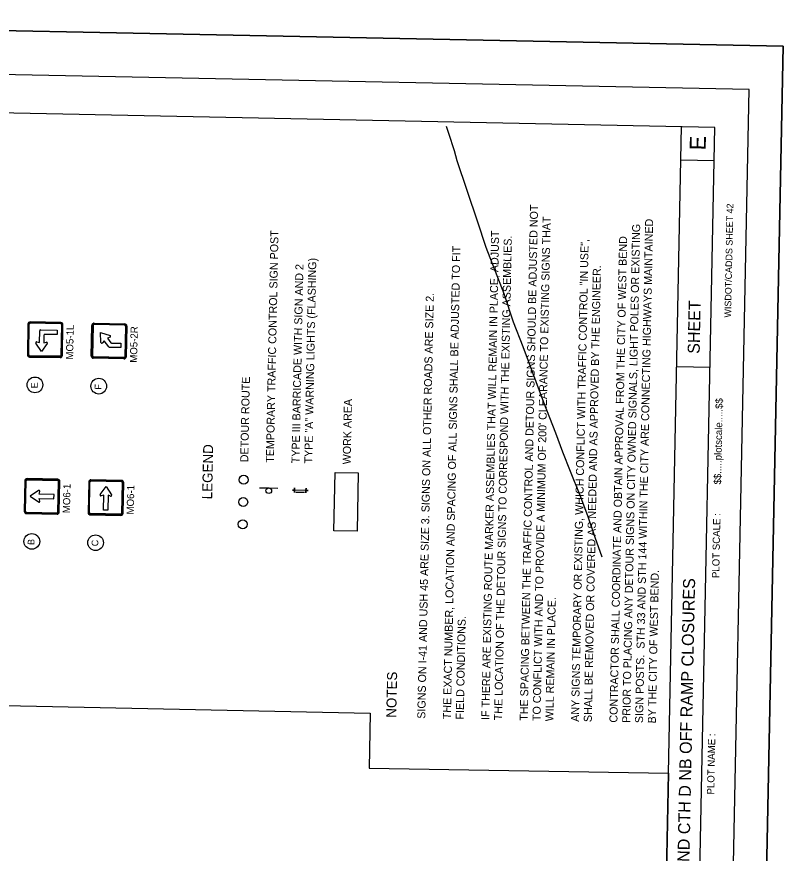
# Model space of a CAD drawing. Extents: x 327762 to 372792, y 127949 to 259367.
# Drawn here: x 358431 to 372792, y 195702 to 211374 of the extents above; entities that cross this region are included whole.
import ezdxf

# ---------------------------------------------------------------- set-up
doc = ezdxf.new("R2010")
doc.units = 0
for name, color, linetype in [('CA-TEXT', 7, 'Continuous'), ('CE-TOPO-CONC-SLAB', 7, 'Continuous'), ('Level 1', 7, 'Continuous'), ('P_MISC_NoPlot', 7, 'Continuous'), ('P_RDWY_Text', 7, 'Continuous'), ('P_SGN_Cell', 7, 'Continuous'), ('P_TC', 7, 'Continuous'), ('PLT_Sheet_Border', 7, 'Continuous'), ('PLT_Sheet_Info', 7, 'Continuous'), ('SIGNS-POLES', 7, 'Continuous')]:
    doc.layers.add(name, color=color, linetype=linetype)

msp = doc.modelspace()

# ---------------------------------------------------------------- linework, layer by layer
at = {"layer": 'CA-TEXT'}
for centre in [(358773, 204477), (359968, 204453), (358714, 201544), (359909, 201520)]:
    msp.add_circle(centre, 147, dxfattribs=at)
at = {"layer": 'CE-TOPO-CONC-SLAB'}
for centre in [(362683, 202699), (362674, 202282), (362666, 201865)]:
    msp.add_circle(centre, 83.7, dxfattribs=at)
at = {"layer": 'Level 1'}
for points in [[(367735, 205650), (367564, 206185), (367228, 207053), (367066, 207544), (366680, 208672), (366630, 208860), (366529, 209184), (366482, 209319)], [(369268, 201620), (369131, 202025), (368989, 202402), (368805, 202851), (368663, 203217), (368530, 203572), (368306, 204147), (368164, 204534), (368103, 204701), (367920, 205192), (367735, 205650)], [(369401, 201251), (369268, 201620)]]:
    msp.add_lwpolyline(points, dxfattribs=at)
at = {"layer": 'P_MISC_NoPlot'}
msp.add_lwpolyline([(345724, 170440), (346294, 198721), (365051, 198328), (365036, 197298), (370642, 197202), (370093, 169949)], close=True, dxfattribs=at)
at = {"layer": 'P_RDWY_Text'}
msp.add_lwpolyline([(344443, 168885), (345298, 211374), (372792, 210820), (371936, 168331)], close=True, dxfattribs=at)
at = {"layer": 'P_SGN_Cell'}
for p, q in [((359258, 205644), (358684, 205656)), ((359258, 205633), (358684, 205645)), ((359258, 205619), (358684, 205631)), ((359879, 205631), (360454, 205620)), ((358642, 205615), (358631, 205041)), ((358642, 205041), (358653, 205615)), ((358655, 205041), (358667, 205615)), ((358857, 205268), (358861, 205491)), ((358878, 205507), (359190, 205500)), ((359190, 205500), (359188, 205418)), ((359262, 205029), (359274, 205603)), ((359276, 205028), (359288, 205602)), ((359287, 205028), (359298, 205602)), ((359826, 205017), (359838, 205591)), ((359849, 205591), (359837, 205017)), ((359862, 205591), (359851, 205017)), ((360453, 205609), (359879, 205621)), ((360453, 205595), (359879, 205607)), ((360469, 205579), (360458, 205005)), ((360483, 205578), (360471, 205004)), ((360494, 205578), (360482, 205004)), ((358942, 205410), (358939, 205266)), ((359188, 205418), (358956, 205423)), ((360009, 205272), (360001, 205459)), ((360001, 205459), (360179, 205399)), ((360180, 205369), (360133, 205352)), ((360133, 205352), (360197, 205267)), ((358895, 205102), (358791, 205258)), ((358810, 205283), (358857, 205268)), ((359004, 205254), (358895, 205102)), ((358939, 205266), (358986, 205280)), ((360068, 205302), (360038, 205263)), ((360154, 205188), (360068, 205302)), ((360379, 205176), (360169, 205180)), ((360208, 205261), (360381, 205258)), ((360381, 205258), (360379, 205176)), ((359245, 204999), (358671, 205010)), ((358671, 204999), (359245, 204988)), ((359246, 205013), (358672, 205024)), ((360441, 204988), (359867, 205000)), ((360441, 204975), (359866, 204986)), ((360440, 204964), (359866, 204975)), ((358583, 202682), (358572, 202108)), ((358583, 202108), (358594, 202682)), ((358596, 202107), (358608, 202681)), ((359199, 202710), (358625, 202722)), ((358625, 202711), (359199, 202700)), ((358625, 202697), (359199, 202686)), ((359203, 202095), (359215, 202669)), ((359217, 202095), (359228, 202669)), ((359228, 202095), (359239, 202669)), ((359779, 202658), (359767, 202084)), ((359778, 202083), (359789, 202658)), ((359792, 202083), (359803, 202657)), ((360394, 202686), (359820, 202698)), ((360394, 202675), (359820, 202687)), ((360394, 202662), (359820, 202673)), ((358841, 202496), (358684, 202393)), ((359995, 202423), (360105, 202575)), ((360105, 202575), (360208, 202419)), ((360398, 202071), (360410, 202645)), ((360412, 202071), (360424, 202645)), ((360423, 202070), (360435, 202645)), ((358684, 202393), (358837, 202283)), ((358862, 202301), (358849, 202348)), ((358849, 202348), (359129, 202343)), ((358850, 202430), (358866, 202477)), ((359131, 202425), (358850, 202430)), ((359129, 202343), (359131, 202425)), ((360061, 202411), (360013, 202397)), ((360055, 202131), (360061, 202411)), ((360143, 202409), (360137, 202129)), ((360190, 202394), (360143, 202409)), ((358612, 202091), (359187, 202079)), ((358612, 202077), (359186, 202065)), ((358612, 202066), (359186, 202054)), ((360381, 202041), (359807, 202053)), ((359807, 202042), (360381, 202030)), ((360382, 202055), (359808, 202066)), ((360137, 202129), (360055, 202131))]:
    msp.add_line(p, q, dxfattribs=at)
for centre, radius, start, end in [((358683, 205615), 41, 88.8462, 178.8462), ((358683, 205615), 30.1, 88.8462, 178.8462), ((358683, 205615), 16.4, 88.8462, 178.8462), ((359257, 205603), 41, 358.8462, 88.8462), ((359257, 205603), 30.1, 358.8462, 88.8462), ((359879, 205590), 41, 88.8462, 178.8462), ((359879, 205590), 41, 88.8462, 113.5578), ((358878, 205490), 16.4, 88.8462, 178.8462), ((359257, 205603), 16.4, 358.8462, 88.8462), ((359879, 205590), 41, 144.5056, 178.8462), ((359879, 205590), 30.1, 88.8462, 178.8462), ((359879, 205590), 16.4, 88.8462, 178.8462), ((360453, 205579), 30.1, 358.8462, 88.8462), ((360453, 205579), 16.4, 358.8462, 88.8462), ((360453, 205579), 41, 358.8462, 88.8462), ((358955, 205409), 13.7, 88.8462, 178.8462), ((360174, 205384), 16.4, 290.0436, 71.3759), ((358805, 205268), 16.4, 72.0436, 213.3759), ((358991, 205264), 16.4, 324.3166, 105.6488), ((360025, 205272), 16.4, 182.3166, 323.6488), ((360169, 205199), 19.1, 216.8459, 268.8462), ((360208, 205275), 13.7, 216.8461, 268.8462), ((358672, 205040), 41, 178.8462, 268.8462), ((358672, 205040), 30.1, 178.8462, 268.8462), ((358672, 205040), 16.4, 178.8462, 268.8462), ((359246, 205029), 30.1, 268.8462, 358.8462), ((359246, 205029), 41, 268.8462, 358.8462), ((359246, 205029), 16.4, 268.8462, 358.8462), ((359867, 205016), 41, 178.8462, 268.8462), ((359867, 205016), 30.1, 178.8462, 268.8462), ((359867, 205016), 16.4, 178.8462, 268.8462), ((360441, 205005), 41, 268.8462, 358.8462), ((360441, 205005), 16.4, 268.8462, 358.8462), ((360441, 205005), 30.1, 268.8462, 358.8462), ((358624, 202681), 41, 88.8462, 178.8462), ((358624, 202681), 41, 149.4497, 178.8462), ((358624, 202681), 30.1, 88.8462, 178.8462), ((358624, 202681), 16.4, 88.8462, 178.8462), ((359198, 202669), 41, 358.8462, 88.8462), ((359198, 202669), 30.1, 358.8462, 88.8462), ((359198, 202669), 16.4, 358.8462, 88.8462), ((359820, 202657), 41, 88.8462, 178.8462), ((359820, 202657), 30.1, 88.8462, 178.8462), ((359820, 202657), 16.4, 88.8462, 178.8462), ((360394, 202645), 41, 358.8462, 88.8462), ((360394, 202645), 30.1, 358.8462, 88.8462), ((360394, 202645), 16.4, 358.8462, 88.8462), ((358850, 202482), 16.4, 342.0436, 123.3759), ((360009, 202413), 16.4, 144.3166, 285.6488), ((360195, 202409), 16.4, 252.0436, 33.3759), ((358846, 202296), 16.4, 234.3166, 15.6488), ((358613, 202107), 41, 178.8462, 268.8462), ((358613, 202107), 30.1, 178.8462, 268.8462), ((358613, 202107), 16.4, 178.8462, 268.8462), ((359187, 202095), 30.1, 268.8462, 358.8462), ((359187, 202095), 41, 268.8462, 358.8462), ((359187, 202095), 16.4, 268.8462, 358.8462), ((359808, 202083), 41, 178.8462, 268.8462), ((359808, 202083), 30.1, 178.8462, 268.8462), ((359808, 202083), 41, 239.4497, 268.8462), ((359808, 202083), 16.4, 178.8462, 268.8462), ((360382, 202071), 30.1, 268.8462, 358.8462), ((360382, 202071), 41, 268.8462, 358.8462), ((360382, 202071), 16.4, 268.8462, 358.8462)]:
    msp.add_arc(centre, radius, start, end, dxfattribs=at)
at = {"layer": 'P_TC'}
for p, q in [((363637, 202504), (363595, 202505)), ((363595, 202505), (363637, 202504)), ((363637, 202504), (363636, 202462)), ((363636, 202462), (363637, 202504)), ((363637, 202504), (363638, 202547)), ((363638, 202547), (363637, 202504)), ((363850, 202500), (363637, 202504)), ((363850, 202500), (363849, 202457)), ((363849, 202457), (363850, 202500)), ((363851, 202542), (363850, 202500)), ((363850, 202500), (363851, 202542)), ((363850, 202500), (363892, 202499)), ((363892, 202499), (363850, 202500)), ((363824, 202458), (363661, 202461))]:
    msp.add_line(p, q, dxfattribs=at)
msp.add_lwpolyline([(364830, 202827), (364808, 201736), (364373, 201745), (364395, 202836)], close=True, dxfattribs=at)
at = {"layer": 'PLT_Sheet_Border'}
for points in [[(371936, 168331), (372792, 210820), (345298, 211374), (344443, 168885)], [(371317, 168643), (372150, 210008), (345907, 210537), (345074, 169172)]]:
    msp.add_lwpolyline(points, close=True, dxfattribs=at)
at = {"layer": 'PLT_Sheet_Info'}
for p, q in [((372792, 210820), (371542, 210846)), ((372767, 209571), (372792, 210820)), ((371511, 209302), (346517, 209806)), ((370093, 169949), (370886, 209315)), ((370718, 169937), (371511, 209302)), ((371498, 208677), (370874, 208690)), ((371420, 204803), (370796, 204816))]:
    msp.add_line(p, q, dxfattribs=at)
at = {"layer": 'SIGNS-POLES'}
for p, q in [((362982, 202548), (363151, 202547)), ((363152, 202546), (363321, 202544))]:
    msp.add_line(p, q, dxfattribs=at)
msp.add_circle((363153, 202494), 52.2, dxfattribs=at)

# ---------------------------------------------------------------- texts
at = {"layer": 'CA-TEXT'}
for s, height, rotation, p in [('THE SPACING BETWEEN THE TRAFFIC CONTROL AND DETOUR SIGNS SHOULD BE ADJUSTED NOT', 149.99, 88.8462, (368004, 198182)), ("TO CONFLICT WITH AND TO PROVIDE A MINIMUM OF 200' CLEARANCE TO EXISTING SIGNS THAT", 149.99, 88.8462, (368244, 198177)), ('SIGN POSTS.  STH 33 AND STH 144 WITHIN THE CITY ARE CONNECTING HIGHWAYS MAINTAINED ', 149.99, 88.8462, (370164, 198139)), ('TEMPORARY TRAFFIC CONTROL SIGN POST', 149.99, 88.8468, (363248, 203016)), ('IF THERE ARE EXISTING ROUTE MARKER ASSEMBLIES THAT WILL REMAIN IN PLACE, ADJUST', 149.99, 88.8462, (367285, 198197)), ('PRIOR TO PLACING ANY DETOUR SIGNS ON CITY OWNED SIGNALS, LIGHT POLES OR EXISTING', 149.99, 88.8462, (369924, 198143)), ('THE LOCATION OF THE DETOUR SIGNS TO CORRESPOND WITH THE EXISTING ASSEMBLIES. ', 149.99, 88.8462, (367524, 198192)), ('CONTRACTOR SHALL COORDINATE AND OBTAIN APPROVAL FROM THE CITY OF WEST BEND', 149.99, 88.8462, (369684, 198148)), ('THE EXACT NUMBER, LOCATION AND SPACING OF ALL SIGNS SHALL BE ADJUSTED TO FIT', 149.99, 88.8462, (366565, 198211)), ('ANY SIGNS TEMPORARY OR EXISTING, WHICH CONFLICT WITH TRAFFIC CONTROL "IN USE",', 149.99, 88.8462, (368964, 198163)), ('TYPE III BARRICADE WITH SIGN AND 2', 149.99, 88.8468, (363728, 203007)), ('TYPE "A" WARNING LIGHTS (FLASHING)', 149.99, 88.8468, (363968, 203002)), ('SHALL BE REMOVED OR COVERED AS NEEDED AND AS APPROVED BY THE ENGINEER.', 149.99, 88.8462, (369204, 198158)), ('SIGNS ON I-41 AND USH 45 ARE SIZE 3. SIGNS ON ALL OTHER ROADS ARE SIZE 2.', 149.99, 88.8462, (366085, 198221)), ('DETOUR ROUTE', 149.99, 88.8468, (362768, 203026)), ('E', 125, 88.8468, (358822, 204411)), ('F', 125, 88.8468, (360017, 204387)), ('WORK AREA', 150, 88.8468, (364687, 202987)), ('LEGEND', 187.5, 88.8468, (362092, 202332)), ('B', 125, 88.8468, (358762, 201477)), ('C', 125, 88.8468, (359958, 201453)), ('BY THE CITY OF WEST BEND.', 149.99, 88.8462, (370404, 198134)), ('WILL REMAIN IN PLACE.', 149.99, 88.8462, (368484, 198172)), ('FIELD CONDITIONS.', 149.99, 88.8462, (366805, 198206)), ('NOTES', 187.5, 88.8468, (365541, 198239))]:
    msp.add_text(s, height=height, rotation=rotation, dxfattribs=at).set_placement(p)
at = {"layer": 'P_SGN_Cell'}
for s, p in [('MO5-1L', (359487, 204950)), ('MO5-2R', (360686, 204891)), ('MO6-1', (359429, 202072)), ('MO6-1', (360624, 202048))]:
    msp.add_text(s, height=135, rotation=88.8462, dxfattribs=at).set_placement(p)
at = {"layer": 'PLT_Sheet_Info'}
for s, height, p in [('E', 300, (371338, 208871)), ('WISDOT/CADDS SHEET 42', 125, (371814, 205738)), ('SHEET ', 225, (371225, 205057)), ('$$.....plotscale.....$$', 134.99, (371626, 202611)), ('PLOT SCALE : ', 134.99, (371591, 200857)), ('DETOUR ROUTE - STH 33 AND CTH D NB OFF RAMP CLOSURES', 224.99, (370954, 191561)), ('PLOT NAME :                      ', 134.99, (371497, 196801))]:
    msp.add_text(s, height=height, rotation=88.8462, dxfattribs=at).set_placement(p)

doc.saveas('drawing.dxf')
